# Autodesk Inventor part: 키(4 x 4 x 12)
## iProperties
IsCustomPart: 0
Created: 2009-02
Part Number: 키(4 x 4 x 12)
Material: 강, 연강
Description: 키 및 해당 키홈
Document SubType Name: Modeling
Standard: KS B 1311
Designer: KYOUNG IL JANG
Standards Organization: KS
Language: ko-KR
Size Designation: 4 x 4 x 12
Categories: <MemberInstance><Categories><Category DisplayName="샤프트 부품" InternalName="7f7aeb1f-a693-4053-b835-cee3144e0d98" Mnemonic="SHFT"><Category DisplayName="키" Interna
Density: 7.86 g/cm^3
Mass: 1.38739 g
Surface Area: 1.94869 cm^2
Volume: 0.176513 cm^3
Author: KYOUNG IL JANG
